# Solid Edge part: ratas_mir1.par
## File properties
Author: Kalle
Template: Iso Part.par
Last saved by: Kalle
Revision: 2
Application: Solid Edge
Accuracy: 0,990
Username: Kalle
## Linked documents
ratas.par
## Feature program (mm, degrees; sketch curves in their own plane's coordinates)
part copy "CopiedPart_1"
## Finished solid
Body 1: solid body, 6 faces, 6 edges, 0 vertices.
  Faces by surface: cylinder 3, plane 3
  Edges by curve: circle 6
Bounding box of the edges (mm): 30.000 x 12.000 x 30.000, from (13.8781, 0, -41.601) to (43.8781, 12, -11.601).
Cylindrical faces by radius (mm): R4 x1, R10 x1, R15 x1
Planar faces by outward normal: +y 2, -y 1
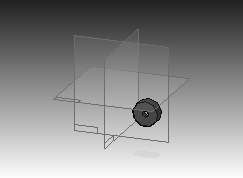
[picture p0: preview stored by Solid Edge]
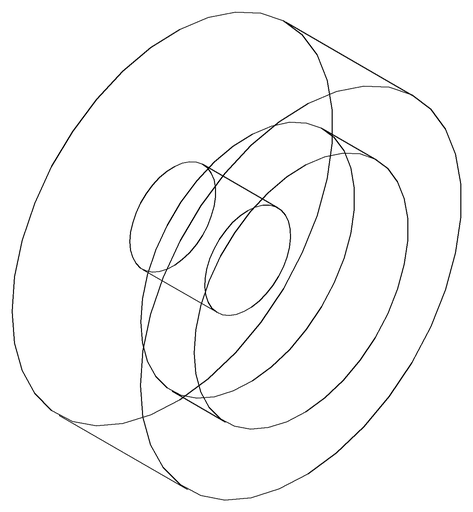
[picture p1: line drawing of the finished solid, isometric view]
